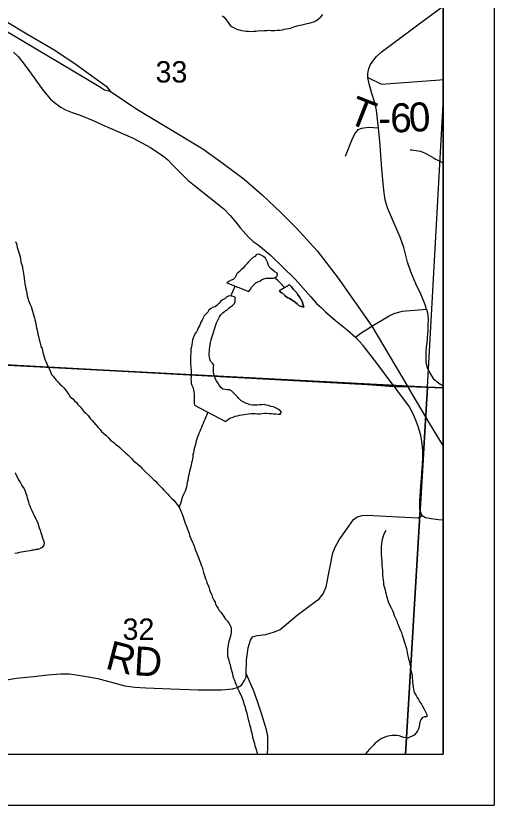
# Model space of a CAD drawing. Extents: x -20.2 to 34, y 0 to 22.
# Drawn here: x 8.064 to 9, y 14 to 15.546 of the extents above; entities that cross this region are included whole.
import ezdxf

# ---------------------------------------------------------------- set-up
doc = ezdxf.new("R2010")
doc.units = 0
for name, color, linetype in [('Default', 7, 'Continuous'), ('GM_X_County_Road', 7, 'Continuous'), ('GM_X_Minor_River', 7, 'Continuous'), ('GM_X_Section_Text', 7, 'Continuous'), ('GM_X_Township_Road', 7, 'Continuous'), ('GM_X_Township_Road_Text', 7, 'Continuous'), ('GM_X_US_Route', 7, 'Continuous'), ('SH_Cut_Line', 7, 'Continuous'), ('SH_Data', 7, 'Continuous')]:
    doc.layers.add(name, color=color, linetype=linetype)

msp = doc.modelspace()

# ---------------------------------------------------------------- linework, layer by layer
at = {"layer": 'Default'}
msp.add_lwpolyline([(7.8018, 14.8755), (8.7518, 14.8242), (8.8043, 14.8205), (8.8307, 14.8199), (8.9, 14.8176), (8.9, 20.9)], dxfattribs=at)
for points in [[(8.9, 15.3734), (8.9, 15.8211), (7.8624, 15.8798), (7.7985, 14.8753), (8.8697, 14.8191)], [(6.677, 14.1), (8.9, 14.1), (8.9, 14.8176), (8.8307, 14.8199), (8.8043, 14.8205), (8.7518, 14.8242), (7.8018, 14.8755), (7.4691, 14.8901), (6.9424, 14.9212), (6.7293, 14.9338), (6.7268, 14.8866), (6.7253, 14.8563), (6.7159, 14.6775), (6.6915, 14.3879), (6.6783, 14.124)], [(7.7534, 14.1), (8.8262, 14.1), (8.8697, 14.8191), (7.7985, 14.8753)], [(8.8262, 14.1), (8.9, 14.1), (8.9, 14.8177), (8.8697, 14.8191)]]:
    msp.add_lwpolyline(points, close=True, dxfattribs=at)
at = {"layer": 'GM_X_County_Road'}
for points in [[(8.8673, 14.9719), (8.8643, 14.9819), (8.8573, 14.9995), (8.8468, 15.0215), (8.8366, 15.0448), (8.8305, 15.0637), (8.8228, 15.0925), (8.8157, 15.113), (8.8026, 15.1424), (8.7913, 15.1701), (8.7868, 15.1855), (8.7847, 15.1996), (8.7825, 15.2179), (8.7803, 15.2467), (8.7764, 15.3005), (8.7737, 15.3265), (8.7693, 15.3614), (8.7661, 15.376), (8.7608, 15.3942), (8.7555, 15.4131), (8.7529, 15.4254), (8.7529, 15.4331), (8.7546, 15.4432), (8.7579, 15.4509), (8.7641, 15.4602), (8.7698, 15.4663), (8.7788, 15.4749), (8.807, 15.4962), (8.8507, 15.5286), (8.9, 15.565)], [(8.8074, 14.8161), (8.8046, 14.82), (8.8004, 14.8256), (8.7704, 14.8659), (8.7438, 14.9006), (8.7288, 14.9165), (8.7416, 14.9265), (8.7496, 14.9315), (8.7607, 14.9383), (8.7945, 14.9587), (8.8045, 14.9629), (8.8201, 14.9675), (8.8673, 14.9719)], [(8.8573, 14.6338), (8.8577, 14.6406), (8.8603, 14.6792), (8.8601, 14.6929), (8.8595, 14.7027), (8.8584, 14.7125), (8.8562, 14.7245), (8.854, 14.7334), (8.8514, 14.7415), (8.8475, 14.7524), (8.8405, 14.7677), (8.8327, 14.782), (8.8126, 14.809), (8.8074, 14.8161)], [(8.9, 14.5585), (8.8992, 14.5586), (8.891, 14.5591), (8.8769, 14.5607), (8.8652, 14.563), (8.859, 14.5666), (8.8562, 14.5731), (8.8542, 14.5788), (8.8547, 14.596), (8.8573, 14.6338)]]:
    msp.add_lwpolyline(points, dxfattribs=at)
at = {"layer": 'GM_X_Minor_River'}
for points in [[(8.4673, 15.5464), (8.4712, 15.5434), (8.4746, 15.5393), (8.4777, 15.5351), (8.4804, 15.5313), (8.4834, 15.5276), (8.4872, 15.5249), (8.4922, 15.5219), (8.4975, 15.5197), (8.5017, 15.5189), (8.5055, 15.5178), (8.5105, 15.5171), (8.5143, 15.5164), (8.5192, 15.516), (8.5241, 15.5157), (8.5291, 15.5161), (8.5336, 15.5165), (8.5374, 15.5169), (8.5412, 15.5177), (8.545, 15.517), (8.5492, 15.5174), (8.5545, 15.5174), (8.5587, 15.5182), (8.5632, 15.5175), (8.567, 15.5175), (8.5708, 15.5175), (8.5754, 15.5179), (8.5807, 15.5184), (8.5853, 15.5188), (8.589, 15.5199), (8.5936, 15.5207), (8.5974, 15.5215), (8.6012, 15.5223), (8.608, 15.5246), (8.6144, 15.5266), (8.6197, 15.5278), (8.6243, 15.5289), (8.6288, 15.5301), (8.6338, 15.5313), (8.6379, 15.5321), (8.6425, 15.5332), (8.6467, 15.5348), (8.652, 15.5371), (8.6561, 15.5402), (8.6606, 15.544), (8.6644, 15.5486)], [(8.8353, 15.2835), (8.8391, 15.2839), (8.8429, 15.2832), (8.8471, 15.2825), (8.8513, 15.2817), (8.8559, 15.281), (8.86, 15.2795), (8.8638, 15.278), (8.8677, 15.2762), (8.8722, 15.2735), (8.8768, 15.2709), (8.8814, 15.2683), (8.8852, 15.2657), (8.8894, 15.2634), (8.8947, 15.2608), (8.8997, 15.2582), (8.9, 15.258)], [(8.0632, 15.1044), (8.0647, 15.0999), (8.0655, 15.0961), (8.0663, 15.0923), (8.0682, 15.0866), (8.0694, 15.0828), (8.0706, 15.0787), (8.0718, 15.0741), (8.0725, 15.0699)], [(8.5755, 15.037), (8.5759, 15.0386), (8.576, 15.04), (8.5751, 15.042), (8.5709, 15.0446), (8.5671, 15.0476), (8.5625, 15.051), (8.5595, 15.0548), (8.5575, 15.059), (8.556, 15.0635), (8.5544, 15.0677), (8.5525, 15.0715), (8.5487, 15.0748), (8.5441, 15.0775), (8.5395, 15.0793), (8.535, 15.0785), (8.5312, 15.0747), (8.527, 15.0724), (8.5233, 15.0686), (8.5191, 15.0644), (8.5157, 15.0606), (8.512, 15.0563), (8.5086, 15.0521), (8.5048, 15.0487), (8.5007, 15.0449), (8.4965, 15.041), (8.4943, 15.0372), (8.4928, 15.0334), (8.489, 15.03), (8.4852, 15.0284), (8.4807, 15.0257), (8.4769, 15.023), (8.5196, 15.0063), (8.5229, 15.0108), (8.5259, 15.0154), (8.5293, 15.0196), (8.5335, 15.0231), (8.5373, 15.025), (8.5411, 15.0262), (8.5448, 15.0288), (8.549, 15.0308), (8.5535, 15.0323), (8.5581, 15.0327), (8.5627, 15.0324), (8.5672, 15.0324), (8.5714, 15.0338), (8.5738, 15.0354), (8.5755, 15.037)], [(8.5755, 15.037), (8.5759, 15.0386), (8.576, 15.04), (8.5751, 15.042), (8.5709, 15.0446), (8.5671, 15.0476), (8.5625, 15.051), (8.5595, 15.0548), (8.5575, 15.059), (8.556, 15.0635), (8.5544, 15.0677), (8.5525, 15.0715), (8.5487, 15.0748), (8.5441, 15.0775), (8.5395, 15.0793), (8.535, 15.0785), (8.5312, 15.0747), (8.527, 15.0724), (8.5233, 15.0686), (8.5191, 15.0644), (8.5157, 15.0606), (8.512, 15.0563), (8.5086, 15.0521), (8.5048, 15.0487)], [(8.0725, 15.0699), (8.0737, 15.0646), (8.0749, 15.0605), (8.0765, 15.0548), (8.0769, 15.051), (8.0777, 15.0464), (8.0785, 15.0411), (8.0792, 15.0373), (8.0797, 15.0324), (8.0805, 15.0263), (8.0813, 15.021), (8.0824, 15.0157), (8.0832, 15.0111), (8.0844, 15.0066), (8.0852, 15.0024), (8.086, 14.9979), (8.0872, 14.9933), (8.0887, 14.9888), (8.091, 14.9823), (8.0934, 14.9766), (8.0949, 14.9725), (8.0965, 14.9675), (8.0976, 14.963), (8.0988, 14.9588), (8.1, 14.9546), (8.1011, 14.9509), (8.1019, 14.9467), (8.1027, 14.9425), (8.1035, 14.9387), (8.1043, 14.9349), (8.1051, 14.9307), (8.1059, 14.927), (8.107, 14.9224), (8.1078, 14.9182), (8.109, 14.9125), (8.1106, 14.9076), (8.1121, 14.9027), (8.1129, 14.8985), (8.1149, 14.8947), (8.1156, 14.8909), (8.1168, 14.8871), (8.118, 14.8826), (8.1191, 14.8784), (8.1207, 14.8735), (8.1223, 14.8689), (8.1242, 14.8648), (8.1257, 14.861), (8.128, 14.8565), (8.13, 14.8519), (8.1319, 14.8477), (8.1335, 14.844), (8.1369, 14.8402), (8.1396, 14.8364), (8.143, 14.8322), (8.1465, 14.8285), (8.1499, 14.8247), (8.1537, 14.8213), (8.1576, 14.8175), (8.1606, 14.8134), (8.1633, 14.8096), (8.1675, 14.8043), (8.1702, 14.7998), (8.1752, 14.796), (8.1786, 14.7922), (8.1825, 14.7888), (8.1848, 14.7851), (8.1897, 14.7802), (8.1928, 14.7764), (8.197, 14.7715), (8.2005, 14.7677), (8.2051, 14.7632), (8.2093, 14.7575), (8.2131, 14.7537), (8.2166, 14.7496), (8.2204, 14.745), (8.2246, 14.7401), (8.2284, 14.736), (8.2315, 14.7322), (8.2357, 14.7284), (8.2395, 14.725), (8.2449, 14.7198), (8.2491, 14.7152), (8.2552, 14.7107), (8.259, 14.7073), (8.2632, 14.7039), (8.2674, 14.7005), (8.272, 14.6964), (8.2785, 14.6904), (8.2827, 14.6862), (8.2869, 14.6821), (8.2907, 14.6787), (8.2942, 14.6745), (8.2984, 14.6711), (8.303, 14.6677), (8.3068, 14.664), (8.3103, 14.6602), (8.3148, 14.6557), (8.3187, 14.6519), (8.3244, 14.6462), (8.3286, 14.6425), (8.3332, 14.6383)], [(8.5048, 15.0487), (8.5007, 15.0449), (8.4965, 15.041), (8.4943, 15.0372), (8.4928, 15.0334), (8.489, 15.03), (8.4852, 15.0284), (8.4807, 15.0257), (8.4769, 15.023), (8.5196, 15.0063), (8.5229, 15.0108), (8.5259, 15.0154), (8.5293, 15.0196), (8.5335, 15.0231), (8.5373, 15.025), (8.5411, 15.0262), (8.5448, 15.0288), (8.549, 15.0308), (8.5535, 15.0323), (8.5581, 15.0327), (8.5627, 15.0324), (8.5672, 15.0324), (8.5714, 15.0338), (8.5738, 15.0354), (8.5755, 15.037)], [(8.5897, 15.0139), (8.5806, 15.0242), (8.5764, 15.0279), (8.5725, 15.0309), (8.5702, 15.0334)], [(8.4843, 14.9973), (8.4884, 15.0064), (8.4928, 15.0168)], [(8.6276, 14.9755), (8.6253, 14.9819), (8.6238, 14.9865), (8.6214, 14.991), (8.6187, 14.9956), (8.6157, 14.9997), (8.6134, 15.0035), (8.6095, 15.0073), (8.6065, 15.0111), (8.6034, 15.0152), (8.5996, 15.0194), (8.5795, 15.0082)], [(8.5795, 15.0082), (8.5996, 15.0194), (8.6034, 15.0152), (8.6065, 15.0111), (8.6095, 15.0073), (8.6134, 15.0035), (8.6157, 14.9997), (8.6187, 14.9956), (8.6214, 14.991), (8.6238, 14.9865), (8.6253, 14.9819), (8.6273, 14.9755), (8.6276, 14.9755), (8.6227, 14.977), (8.6181, 14.9785), (8.6143, 14.9819), (8.6105, 14.9856), (8.6067, 14.9883), (8.6028, 14.9905), (8.599, 14.9928), (8.5948, 14.9943), (8.5902, 14.9984), (8.586, 15.0022), (8.5822, 15.0044), (8.5795, 15.0082)], [(8.5795, 15.0082), (8.5822, 15.0044), (8.586, 15.0022), (8.5902, 14.9984), (8.5948, 14.9943), (8.599, 14.9928), (8.6028, 14.9905), (8.6067, 14.9883), (8.6105, 14.9856), (8.6143, 14.9819), (8.6181, 14.9785), (8.6227, 14.977), (8.6276, 14.9755)], [(8.4851, 14.9973), (8.4809, 14.9976), (8.4764, 14.9957), (8.4726, 14.9922), (8.468, 14.9899), (8.4643, 14.9869), (8.4613, 14.983), (8.4575, 14.9792), (8.4537, 14.9765), (8.4499, 14.9754), (8.4454, 14.9731), (8.4416, 14.97), (8.4397, 14.9658), (8.436, 14.9624), (8.4322, 14.9585), (8.4303, 14.9547), (8.4281, 14.9501), (8.4258, 14.9463), (8.4243, 14.9425), (8.4229, 14.9387), (8.4206, 14.9349), (8.4191, 14.9311), (8.4172, 14.9273), (8.4142, 14.9231), (8.4124, 14.9193), (8.4109, 14.9154), (8.4094, 14.9109), (8.409, 14.9067), (8.4083, 14.9021), (8.4072, 14.8976), (8.4065, 14.893), (8.4061, 14.8888), (8.4062, 14.8843), (8.4058, 14.8801), (8.4055, 14.8759), (8.4055, 14.8713), (8.4055, 14.8675), (8.4056, 14.8637), (8.406, 14.86), (8.406, 14.8562), (8.4068, 14.8516), (8.4068, 14.8474), (8.4069, 14.8436), (8.4069, 14.8391), (8.4065, 14.8345), (8.4066, 14.8307), (8.407, 14.8265), (8.4082, 14.8227), (8.4105, 14.8178), (8.4113, 14.8133), (8.412, 14.8095), (8.4125, 14.8057), (8.4125, 14.8011), (8.4125, 14.7973), (8.4129, 14.7931), (8.413, 14.7874), (8.4134, 14.7833), (8.474, 14.7518)], [(8.474, 14.7518), (8.477, 14.7545), (8.4808, 14.7571), (8.4846, 14.7587), (8.4891, 14.7602), (8.4929, 14.7618), (8.4974, 14.763), (8.5012, 14.7641), (8.5058, 14.7645), (8.5103, 14.7653), (8.5145, 14.7661), (8.5191, 14.7665), (8.5236, 14.7673), (8.5282, 14.7674), (8.532, 14.767), (8.5365, 14.7667), (8.5411, 14.7667), (8.546, 14.7671), (8.5506, 14.7679), (8.5551, 14.7679), (8.5597, 14.7676), (8.5635, 14.7672), (8.568, 14.7665), (8.5726, 14.7669), (8.5772, 14.7662), (8.581, 14.7662), (8.5836, 14.77), (8.5798, 14.7742), (8.5759, 14.7764), (8.5721, 14.7787), (8.5679, 14.7802), (8.563, 14.7813), (8.5584, 14.7828), (8.5535, 14.7835), (8.5497, 14.7846), (8.5451, 14.7842), (8.5406, 14.7842), (8.536, 14.7838), (8.5315, 14.7833), (8.5269, 14.7833), (8.5224, 14.784), (8.5178, 14.7863), (8.5132, 14.7878), (8.5086, 14.7904), (8.5048, 14.7923), (8.5002, 14.7964), (8.4975, 14.8002), (8.4937, 14.8036), (8.4895, 14.8077), (8.4861, 14.8115), (8.4819, 14.8134), (8.4781, 14.8137), (8.4735, 14.8145), (8.469, 14.8152), (8.4648, 14.8182), (8.4617, 14.8227), (8.459, 14.8273), (8.4567, 14.8314), (8.4536, 14.836), (8.4524, 14.8401), (8.4513, 14.8443), (8.4505, 14.8489), (8.4504, 14.8538), (8.4508, 14.8584), (8.4511, 14.8622), (8.4488, 14.866), (8.445, 14.8697), (8.4431, 14.8735), (8.4427, 14.8777), (8.4423, 14.8815), (8.4422, 14.8853), (8.4426, 14.8891), (8.4429, 14.8933), (8.4437, 14.8971), (8.444, 14.9016), (8.4447, 14.9062), (8.4458, 14.9115), (8.4473, 14.9161), (8.4484, 14.9199), (8.4499, 14.9241), (8.4514, 14.9283), (8.4525, 14.9328), (8.4536, 14.937), (8.4551, 14.9408), (8.4562, 14.9446), (8.4581, 14.9485), (8.4603, 14.953), (8.4626, 14.9568), (8.4652, 14.9607), (8.469, 14.9645), (8.4728, 14.9676), (8.4765, 14.9699), (8.4803, 14.9737), (8.4841, 14.976), (8.4879, 14.9787), (8.4916, 14.9829), (8.4927, 14.9867), (8.4931, 14.9905), (8.4927, 14.9951), (8.4889, 14.9962), (8.4851, 14.9973)], [(8.4395, 14.7697), (8.4337, 14.7557), (8.4318, 14.7515), (8.4304, 14.7477), (8.4285, 14.7439), (8.427, 14.7401), (8.4251, 14.7359), (8.424, 14.7321), (8.4221, 14.7282), (8.4203, 14.724), (8.4188, 14.7195), (8.4173, 14.7153), (8.4162, 14.7111), (8.4151, 14.7065), (8.414, 14.7027), (8.4129, 14.6989), (8.4121, 14.6944), (8.4114, 14.6902), (8.4103, 14.686), (8.41, 14.6822), (8.4092, 14.6784), (8.4085, 14.6746), (8.4078, 14.6708), (8.407, 14.6666), (8.4063, 14.6628), (8.4048, 14.6586), (8.4037, 14.6544), (8.403, 14.6495), (8.4019, 14.6457), (8.4008, 14.6411), (8.4, 14.6365), (8.3993, 14.6323), (8.3986, 14.6274), (8.3979, 14.6232), (8.3964, 14.619), (8.3949, 14.6152), (8.393, 14.611), (8.3911, 14.6072), (8.3893, 14.6026), (8.3882, 14.5984), (8.3871, 14.5946), (8.3831, 14.584)], [(8.0624, 14.6516), (8.0643, 14.6467), (8.067, 14.6421), (8.0689, 14.6376), (8.072, 14.633), (8.0743, 14.6289), (8.077, 14.624), (8.0797, 14.6198), (8.0816, 14.6149), (8.0835, 14.6107), (8.0851, 14.6062), (8.0859, 14.6024), (8.0874, 14.5982), (8.0886, 14.5944), (8.0894, 14.5906), (8.0909, 14.5861), (8.0929, 14.5811), (8.0948, 14.5774), (8.0967, 14.5728), (8.0987, 14.569), (8.101, 14.5645), (8.1029, 14.5607), (8.1045, 14.5569), (8.1068, 14.5524), (8.1079, 14.5478), (8.1095, 14.5433), (8.111, 14.5387), (8.1126, 14.5342), (8.1138, 14.5304), (8.1153, 14.5258), (8.1165, 14.522), (8.1177, 14.5183), (8.1188, 14.5141), (8.1185, 14.5095), (8.1155, 14.5049), (8.1113, 14.503), (8.1068, 14.5011), (8.103, 14.5007), (8.0992, 14.4999), (8.0954, 14.4995), (8.0916, 14.4983), (8.0867, 14.4975), (8.0829, 14.4967), (8.0787, 14.4963), (8.0749, 14.4955), (8.0704, 14.4947), (8.0662, 14.4939), (8.062, 14.4928)], [(8.3332, 14.6383), (8.337, 14.6349), (8.3412, 14.6304), (8.3458, 14.6259), (8.35, 14.6213), (8.3531, 14.6172), (8.3569, 14.6138), (8.3604, 14.61), (8.3638, 14.6059), (8.3684, 14.6013), (8.373, 14.5972), (8.3761, 14.593), (8.3795, 14.5889), (8.3826, 14.5847), (8.3849, 14.5809), (8.3868, 14.576), (8.3884, 14.5722), (8.3899, 14.5684), (8.3911, 14.5647), (8.3926, 14.5601), (8.3938, 14.5563), (8.3954, 14.5525), (8.3973, 14.5476), (8.3988, 14.5427), (8.4, 14.5385), (8.4027, 14.5328), (8.4039, 14.5283), (8.4062, 14.5226), (8.4085, 14.5165), (8.4105, 14.5124), (8.4128, 14.5071), (8.4147, 14.501), (8.417, 14.4953), (8.4194, 14.4896), (8.4209, 14.4855), (8.4232, 14.4794), (8.4252, 14.4745), (8.4267, 14.4703), (8.4283, 14.4661), (8.4298, 14.4608), (8.431, 14.4559), (8.4322, 14.4521), (8.4337, 14.4479), (8.4349, 14.4434), (8.4368, 14.4396), (8.4376, 14.4354), (8.4399, 14.4309), (8.4419, 14.426), (8.443, 14.4214), (8.445, 14.4169), (8.4473, 14.4119), (8.4488, 14.407), (8.4512, 14.4017), (8.4535, 14.3976), (8.4546, 14.3938), (8.4569, 14.3892), (8.4596, 14.3854), (8.4619, 14.3817), (8.465, 14.3779), (8.4681, 14.3737), (8.4708, 14.3699), (8.4742, 14.3646), (8.4777, 14.3605), (8.4807, 14.3563), (8.483, 14.3522), (8.485, 14.3484), (8.4854, 14.3434), (8.4854, 14.3389), (8.4847, 14.3347), (8.4836, 14.3309), (8.4828, 14.3271), (8.4814, 14.3225), (8.4799, 14.318), (8.4791, 14.3141), (8.4784, 14.3096), (8.4781, 14.3058), (8.4777, 14.3005), (8.4778, 14.2967), (8.4782, 14.2921), (8.4793, 14.2879), (8.4805, 14.2841), (8.4813, 14.28), (8.4829, 14.275), (8.484, 14.2709), (8.4852, 14.2663), (8.4867, 14.2622), (8.4875, 14.2576), (8.4887, 14.2531), (8.4899, 14.2489), (8.4914, 14.2451), (8.493, 14.2402), (8.4949, 14.236), (8.4968, 14.2318), (8.4984, 14.2277), (8.5003, 14.2239), (8.5023, 14.2197), (8.5046, 14.2152), (8.5061, 14.211), (8.508, 14.2065), (8.5092, 14.2019), (8.5108, 14.1974)], [(8.7877, 14.5382), (8.7851, 14.5336), (8.7832, 14.5287), (8.7821, 14.5249), (8.781, 14.5207), (8.7803, 14.5169), (8.7792, 14.5116), (8.7788, 14.5074), (8.7785, 14.5024), (8.7789, 14.4979), (8.7789, 14.4933), (8.7789, 14.4895), (8.7794, 14.4846), (8.7798, 14.4781), (8.7798, 14.4736), (8.7802, 14.4698), (8.7807, 14.4645), (8.7811, 14.4607), (8.7815, 14.455), (8.7815, 14.4504), (8.7819, 14.4462), (8.7827, 14.4406), (8.7831, 14.4368), (8.7836, 14.4326), (8.7851, 14.4257), (8.7863, 14.422), (8.7871, 14.4174), (8.7886, 14.4132), (8.7894, 14.4094), (8.7906, 14.4053), (8.7921, 14.4007), (8.7933, 14.3969), (8.7952, 14.3928), (8.7976, 14.3882), (8.7995, 14.3841), (8.8014, 14.3803), (8.803, 14.3761), (8.8045, 14.3716), (8.8072, 14.3651), (8.8091, 14.3613), (8.8103, 14.3575), (8.8126, 14.3519), (8.8149, 14.3469), (8.8169, 14.342), (8.8184, 14.3382), (8.82, 14.3333), (8.8219, 14.3272), (8.8231, 14.3234), (8.8243, 14.3189), (8.8258, 14.3147), (8.827, 14.3109), (8.8282, 14.3071), (8.8289, 14.3033), (8.8297, 14.2992), (8.8305, 14.295), (8.8317, 14.2901), (8.8325, 14.2859), (8.834, 14.2806), (8.8348, 14.276), (8.836, 14.2707), (8.8368, 14.265), (8.8376, 14.2612), (8.8388, 14.2571), (8.8392, 14.2529), (8.8392, 14.2491), (8.84, 14.2449), (8.8404, 14.2404), (8.8408, 14.2362), (8.8412, 14.2316), (8.842, 14.2271), (8.8428, 14.2233), (8.8448, 14.2191), (8.8474, 14.215), (8.8494, 14.2112), (8.8521, 14.207), (8.8544, 14.2021), (8.8574, 14.1979), (8.8598, 14.1938), (8.8624, 14.1892), (8.8644, 14.1854), (8.8663, 14.1817), (8.8682, 14.1775), (8.8683, 14.1729), (8.8637, 14.1729), (8.8592, 14.171), (8.8562, 14.1671), (8.8543, 14.1633), (8.8536, 14.1588), (8.8532, 14.1542), (8.8517, 14.1496), (8.8499, 14.1458), (8.8472, 14.1416), (8.8431, 14.1374), (8.8393, 14.1351), (8.8351, 14.1332), (8.831, 14.1316), (8.8268, 14.132), (8.823, 14.1327), (8.8192, 14.1338), (8.8142, 14.1357), (8.8097, 14.1364)], [(8.5108, 14.1974), (8.5123, 14.1924), (8.5135, 14.1883), (8.5147, 14.1841), (8.5155, 14.1803), (8.5174, 14.1735), (8.5186, 14.1678), (8.5198, 14.1636), (8.5213, 14.1579), (8.5229, 14.1522), (8.5237, 14.1477), (8.5252, 14.1431), (8.5264, 14.1382), (8.5272, 14.1333), (8.528, 14.1295), (8.5292, 14.1249), (8.5307, 14.1211), (8.5315, 14.1166), (8.5327, 14.1128), (8.5342, 14.109), (8.5354, 14.1041), (8.5364, 14.1)], [(8.8097, 14.1364), (8.8051, 14.1364), (8.8006, 14.1364), (8.796, 14.1356), (8.7915, 14.1352), (8.7877, 14.134), (8.7828, 14.132), (8.779, 14.1301), (8.7748, 14.1274), (8.7707, 14.1244), (8.7669, 14.1217), (8.7635, 14.1179), (8.759, 14.1133), (8.7552, 14.1094), (8.7518, 14.1052), (8.7488, 14.1014), (8.748, 14.1)]]:
    msp.add_lwpolyline(points, dxfattribs=at)
at = {"layer": 'GM_X_Township_Road'}
for points in [[(8.059, 15.4751), (8.0684, 15.4666), (8.0797, 15.4518), (8.0909, 15.4366), (8.1178, 15.3991), (8.1318, 15.3832), (8.1429, 15.3736), (8.1514, 15.3673), (8.161, 15.3622), (8.174, 15.357), (8.1893, 15.3514), (8.2148, 15.3411), (8.2335, 15.333), (8.2936, 15.3065), (8.327, 15.2884), (8.3536, 15.271), (8.361, 15.2644), (8.3708, 15.2537), (8.3865, 15.2378), (8.4002, 15.2241), (8.4132, 15.2138), (8.4708, 15.1681), (8.4832, 15.1553), (8.4941, 15.1422), (8.5037, 15.1306), (8.5191, 15.113), (8.5283, 15.1045), (8.5381, 15.0975), (8.5616, 15.0781), (8.6104, 15.0304), (8.6414, 14.9956), (8.6523, 14.9829), (8.661, 14.9749), (8.6695, 14.9666), (8.6892, 14.9497), (8.7124, 14.9309), (8.7288, 14.9165)], [(8.7529, 15.4254), (8.7796, 15.4127), (8.8934, 15.4209), (8.9, 15.4215)], [(8.7737, 15.3265), (8.7542, 15.3276), (8.7405, 15.3258), (8.7333, 15.3227), (8.7285, 15.3177), (8.7223, 15.3054), (8.7082, 15.2704)], [(8.8673, 14.9719), (8.8696, 14.9643), (8.8707, 14.9527), (8.8701, 14.9382), (8.8701, 14.93), (8.869, 14.9162), (8.8687, 14.9132)], [(8.8687, 14.9132), (8.8665, 14.8902), (8.8661, 14.8757), (8.8661, 14.8669), (8.8687, 14.8577), (8.8734, 14.8476), (8.8808, 14.8361), (8.8914, 14.8269), (8.9, 14.8217)], [(8.5564, 14.1), (8.5572, 14.1125), (8.5568, 14.135), (8.5546, 14.1479), (8.5447, 14.1795), (8.5392, 14.195), (8.5301, 14.2221), (8.5147, 14.2583), (8.5152, 14.2844), (8.5186, 14.3084), (8.5228, 14.3232), (8.5269, 14.3295), (8.5358, 14.3323), (8.553, 14.3347), (8.5697, 14.3396), (8.5809, 14.3442), (8.6144, 14.3723), (8.635, 14.3881), (8.6571, 14.4041), (8.6655, 14.414), (8.6712, 14.4277), (8.684, 14.4944), (8.6894, 14.507), (8.6965, 14.5199), (8.7107, 14.5399), (8.7249, 14.5599), (8.7315, 14.5648), (8.7416, 14.5678), (8.7508, 14.568), (8.8505, 14.5626), (8.859, 14.5666)], [(8.0413, 14.2448), (8.0651, 14.2487), (8.0984, 14.2522), (8.1261, 14.2552), (8.1514, 14.2572), (8.1688, 14.2574), (8.1941, 14.2537), (8.2239, 14.248), (8.2773, 14.2341), (8.2967, 14.2315), (8.3178, 14.2299), (8.3671, 14.2278), (8.4207, 14.2262), (8.466, 14.226), (8.4878, 14.228), (8.4978, 14.2304), (8.5052, 14.2352), (8.5115, 14.2443), (8.5143, 14.2506), (8.5147, 14.2583)]]:
    msp.add_lwpolyline(points, dxfattribs=at)
at = {"layer": 'GM_X_US_Route'}
msp.add_line((8.3234, 15.3498), (8.3491, 15.3342), dxfattribs=at)
for points in [[(8.0442, 15.5361), (8.0854, 15.5108), (8.1399, 15.479), (8.1815, 15.4512), (8.2404, 15.4085), (8.2483, 15.3986)], [(8.0411, 15.5189), (8.1696, 15.4424), (8.2295, 15.4064)], [(8.2295, 15.4064), (8.2375, 15.4016), (8.2483, 15.3986)], [(8.2483, 15.3986), (8.2986, 15.3648), (8.3234, 15.3498)], [(8.3491, 15.3342), (8.4294, 15.2854), (8.4697, 15.257), (8.5103, 15.2261), (8.5458, 15.1957), (8.5833, 15.1606), (8.6132, 15.1303), (8.6532, 15.0861), (8.6946, 15.0325), (8.7607, 14.9383)], [(8.7607, 14.9383), (8.8309, 14.8194), (8.8322, 14.8171), (8.8726, 14.7485), (8.9, 14.7032)]]:
    msp.add_lwpolyline(points, dxfattribs=at)
at = {"layer": 'SH_Cut_Line'}
msp.add_lwpolyline([(5.7735, 14.1), (8.9, 14.1), (8.9, 20.9), (2.1, 20.9), (2.1, 14.1), (5.3953, 14.1), (5.7268, 14.1076)], close=True, dxfattribs=at)
at = {"layer": 'SH_Data'}
for p, q in [((9, 21), (9, 14)), ((8.9, 20.9), (8.9, 14.1)), ((2.1, 14.1), (8.9, 14.1)), ((2, 14), (9, 14))]:
    msp.add_line(p, q, dxfattribs=at)

# ---------------------------------------------------------------- texts
at = {"layer": 'GM_X_Section_Text'}
for s, p in [('33', (8.3371, 15.4156)), ('32', (8.2725, 14.3239))]:
    msp.add_text(s, height=0.04186, rotation=0, dxfattribs=at).set_placement(p)
at = {"layer": 'GM_X_Township_Road_Text'}
for s, rotation, p in [('T', 338.4819, (8.7103, 15.3377)), ('6', 0.8672, (8.7968, 15.3179)), ('0', 3.4232, (8.8346, 15.3186)), ('-', 0.4205, (8.773, 15.3178)), ('R', 345.4658, (8.2367, 14.2683)), ('D', 356.5927, (8.2936, 14.2548))]:
    msp.add_text(s, height=0.0568, rotation=rotation, dxfattribs=at).set_placement(p)

doc.saveas('drawing.dxf')
